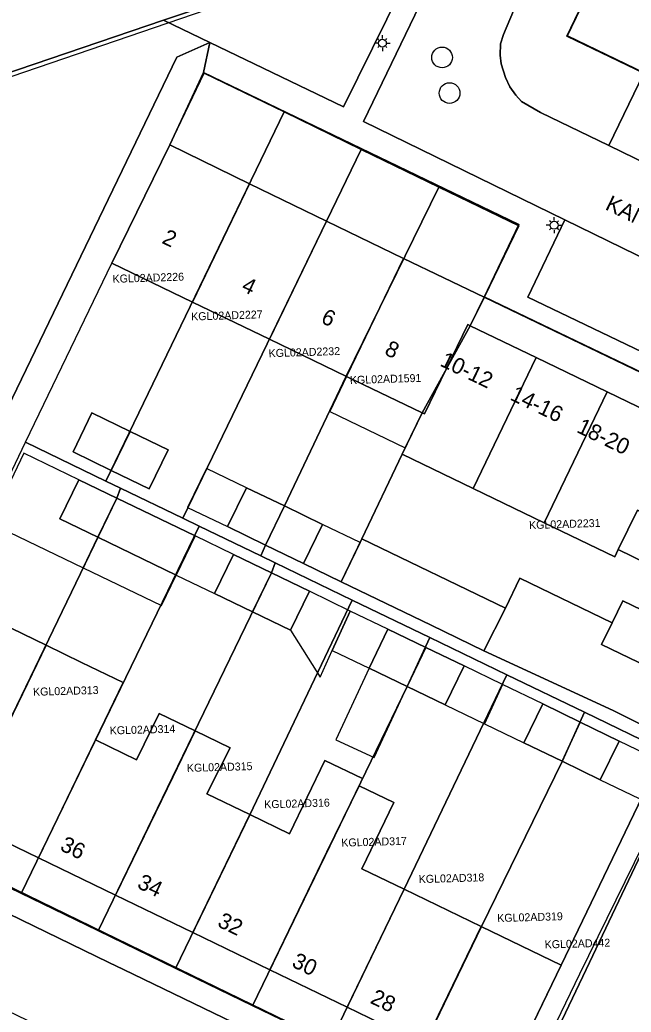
# Model space of a CAD drawing. Extents: x 124901 to 125496, y 515369 to 515789.
# Drawn here: x 125237.2 to 125275.6, y 515497.3 to 515559.7 of the extents above; entities that cross this region are included whole.
import ezdxf

# ---------------------------------------------------------------- set-up
doc = ezdxf.new("R2010")
doc.units = 0
for name, color, linetype in [('Gebouw', 7, 'Continuous'), ('Lichtmast', 7, 'Continuous'), ('Luifel', 7, 'Continuous'), ('Onbegroeid terrein', 7, 'Continuous'), ('Parkeren', 7, 'Continuous'), ('Perceelnummers', 7, 'Continuous'), ('Perceelsgrenzen', 7, 'Continuous'), ('Putten', 7, 'Continuous'), ('Teksten', 7, 'Continuous'), ('Vegetatie', 7, 'Continuous'), ('Voetpad', 7, 'Continuous'), ('Wegen lokale weg', 7, 'Continuous')]:
    doc.layers.add(name, color=color, linetype=linetype)

msp = doc.modelspace()

# ---------------------------------------------------------------- linework, layer by layer
at = {"layer": 'Gebouw'}
for points in [[(125251.606, 515549.402), (125246.6, 515551.84), (125242.94, 515544.4), (125248.008, 515541.962)], [(125252.86, 515539.625), (125256.453, 515547.054), (125251.606, 515549.402), (125248.008, 515541.962)], [(125257.713, 515537.289), (125261.301, 515544.709), (125256.453, 515547.054), (125252.86, 515539.625)], [(125261.301, 515544.709), (125257.713, 515537.289), (125262.47, 515535), (125265.493, 515540.466), (125266.36, 515542.26)], [(125261.21, 515532.39), (125265.676, 515530.239), (125269.642, 515538.465), (125265.493, 515540.466), (125262.47, 515535), (125261.407, 515532.799)], [(125274.106, 515536.313), (125269.642, 515538.465), (125265.676, 515530.239), (125270.14, 515528.089)], [(125277.22, 515531.37), (125278.57, 515534.16), (125274.106, 515536.313), (125270.14, 515528.089), (125274.58, 515525.95), (125274.801, 515526.402), (125276.023, 515528.88), (125278.642, 515527.589), (125279.88, 515530.1)], [(125242.9, 515531.38), (125244.09, 515533.83), (125241.69, 515534.99), (125240.5, 515532.54)], [(125244.09, 515533.83), (125242.9, 515531.38), (125245.3, 515530.22), (125246.49, 515532.67)], [(125243.25, 515529.63), (125240.86, 515530.79), (125239.68, 515528.34), (125242.065, 515527.182)], [(125252.615, 515526.68), (125253.81, 515529.14), (125251.41, 515530.29), (125250.22, 515527.84)], [(125279.717, 515517.905), (125280.762, 515520.078), (125284.72, 515528.31), (125280.11, 515530.54), (125279.88, 515530.1), (125278.642, 515527.589), (125276.023, 515528.88), (125274.801, 515526.402), (125277.47, 515525.11), (125276.256, 515522.602), (125275.09, 515523.17), (125274.418, 515521.801), (125273.75, 515520.44), (125279.58, 515517.62)], [(125243.25, 515529.63), (125242.065, 515527.182), (125246.994, 515524.794), (125248.184, 515527.254)], [(125256.2, 515527.98), (125253.81, 515529.14), (125252.615, 515526.68), (125255.01, 515525.52)], [(125257.38, 515524.38), (125263.03, 515521.64), (125266.35, 515520.04), (125267.7, 515522.72), (125258.68, 515527.07), (125258.567, 515526.835)], [(125252.98, 515524.935), (125250.59, 515526.09), (125249.4, 515523.64), (125251.795, 515522.485)], [(125252.98, 515524.935), (125251.795, 515522.485), (125254.19, 515521.33), (125255.37, 515523.78)], [(125231.937, 515519.018), (125228.44, 515511.8), (125233.472, 515509.364), (125238.814, 515520.386), (125232.953, 515523.225), (125231.109, 515519.419)], [(125262.705, 515520.235), (125260.31, 515521.39), (125259.13, 515518.94), (125261.52, 515517.78)], [(125238.326, 515507.017), (125241.916, 515514.427), (125243.658, 515518.044), (125241.044, 515519.306), (125238.814, 515520.386), (125233.472, 515509.364)], [(125261.52, 515517.78), (125263.92, 515516.63), (125265.1, 515519.08), (125262.705, 515520.235)], [(125272.399, 515515.555), (125270.05, 515516.69), (125268.87, 515514.24), (125271.265, 515513.085)], [(125241.916, 515514.427), (125238.326, 515507.017), (125243.177, 515504.667), (125246.771, 515512.084), (125248.18, 515514.993), (125245.912, 515516.087), (125244.498, 515513.181)], [(125243.177, 515504.667), (125248.033, 515502.323), (125251.623, 515509.733), (125248.91, 515511.048), (125250.387, 515513.928), (125248.18, 515514.993), (125246.771, 515512.084)], [(125274.85, 515514.35), (125272.399, 515515.555), (125271.265, 515513.085), (125273.66, 515511.93)], [(125248.033, 515502.323), (125252.884, 515499.973), (125256.478, 515507.391), (125258.494, 515511.552), (125258.713, 515512.003), (125256.35, 515513.143), (125254.113, 515508.532), (125251.623, 515509.733)], [(125261.332, 515505.044), (125258.673, 515506.33), (125260.689, 515510.489), (125258.494, 515511.552), (125256.478, 515507.391), (125252.884, 515499.973), (125257.74, 515497.62)], [(125262.591, 515495.279), (125266.185, 515502.697), (125261.332, 515505.044), (125257.74, 515497.62)], [(125266.185, 515502.697), (125262.591, 515495.279), (125267.62, 515492.84), (125271.22, 515500.26)]]:
    msp.add_lwpolyline(points, close=True, dxfattribs=at)
at = {"layer": 'Lichtmast'}
for p, q in [((125259.961, 515558.54), (125259.961, 515558.74)), ((125259.661, 515558.241), (125259.461, 515558.24)), ((125259.749, 515558.452), (125259.679, 515558.523)), ((125260.173, 515558.452), (125260.244, 515558.524)), ((125260.261, 515558.24), (125260.461, 515558.24)), ((125259.749, 515558.028), (125259.677, 515557.957)), ((125259.961, 515557.94), (125259.961, 515557.74)), ((125260.173, 515558.028), (125260.243, 515557.957)), ((125270.556, 515547.002), (125270.486, 515547.073)), ((125270.768, 515547.09), (125270.768, 515547.29)), ((125270.98, 515547.002), (125271.051, 515547.074)), ((125270.468, 515546.791), (125270.268, 515546.79)), ((125270.556, 515546.578), (125270.484, 515546.507)), ((125270.768, 515546.49), (125270.768, 515546.29)), ((125270.98, 515546.578), (125271.05, 515546.507)), ((125271.068, 515546.79), (125271.268, 515546.79))]:
    msp.add_line(p, q, dxfattribs=at)
for centre in [(125259.961, 515558.24), (125270.768, 515546.79)]:
    msp.add_circle(centre, 0.25, dxfattribs=at)
at = {"layer": 'Luifel'}
for points in [[(125262.47, 515535), (125257.713, 515537.289), (125256.649, 515535.088), (125261.407, 515532.799)], [(125241.133, 515525.256), (125242.065, 515527.182), (125239.68, 515528.34), (125240.86, 515530.79), (125237.4, 515532.452), (125235.286, 515528.061)], [(125251.41, 515530.29), (125248.903, 515531.503), (125247.713, 515529.053), (125250.22, 515527.84)], [(125258.567, 515526.835), (125256.2, 515527.98), (125255.01, 515525.52), (125257.38, 515524.38)], [(125242.065, 515527.182), (125241.133, 515525.256), (125246.072, 515522.887), (125246.994, 515524.794)], [(125246.994, 515524.794), (125249.4, 515523.64), (125250.59, 515526.09), (125248.184, 515527.254)], [(125254.19, 515521.33), (125256.039, 515518.371), (125256.811, 515520.062), (125257.942, 515522.535), (125255.37, 515523.78)], [(125260.31, 515521.39), (125257.942, 515522.535), (125256.811, 515520.062), (125259.13, 515518.94)], [(125259.13, 515518.94), (125257.038, 515514.439), (125259.448, 515513.319), (125261.52, 515517.78)], [(125266.395, 515515.435), (125267.526, 515517.909), (125265.1, 515519.08), (125263.92, 515516.63)], [(125267.526, 515517.909), (125266.395, 515515.435), (125268.87, 515514.24), (125270.05, 515516.69)], [(125278.251, 515512.708), (125274.85, 515514.35), (125273.66, 515511.93), (125277.13, 515510.255)]]:
    msp.add_lwpolyline(points, close=True, dxfattribs=at)
at = {"layer": 'Onbegroeid terrein'}
for points in [[(125286.39, 515550.48), (125287.283, 515552.328), (125285.12, 515553.38), (125276.89, 515557.33), (125279.14, 515561.97), (125279.58, 515561.75), (125280.85, 515564.41), (125278.06, 515565.76), (125280.2, 515570.2), (125282.34, 515574.64), (125284.5, 515579.14), (125280.805, 515577.895), (125271.575, 515558.685), (125276.419, 515556.359), (125284.626, 515552.418), (125284.179, 515551.548), (125285.039, 515551.133)], [(125251.606, 515549.402), (125256.453, 515547.054), (125261.301, 515544.709), (125266.36, 515542.26), (125268.55, 515546.839), (125248.71, 515556.387), (125246.6, 515551.84)], [(125278.57, 515534.16), (125277.22, 515531.37), (125279.88, 515530.1), (125280.11, 515530.54), (125284.72, 515528.31), (125286.735, 515532.485), (125266.36, 515542.26), (125265.493, 515540.466), (125269.642, 515538.465), (125274.106, 515536.313)], [(125244.09, 515533.83), (125246.49, 515532.67), (125245.3, 515530.22), (125242.9, 515531.38), (125240.5, 515532.54), (125241.69, 515534.99)], [(125240.86, 515530.79), (125243.25, 515529.63), (125248.184, 515527.254), (125246.994, 515524.794), (125242.065, 515527.182), (125239.68, 515528.34)], [(125253.81, 515529.14), (125256.2, 515527.98), (125255.01, 515525.52), (125252.615, 515526.68), (125250.22, 515527.84), (125251.41, 515530.29)], [(125250.59, 515526.09), (125252.98, 515524.935), (125255.37, 515523.78), (125254.19, 515521.33), (125251.795, 515522.485), (125249.4, 515523.64)], [(125263.92, 515516.63), (125261.52, 515517.78), (125259.13, 515518.94), (125260.31, 515521.39), (125262.705, 515520.235), (125265.1, 515519.08)], [(125272.399, 515515.555), (125274.85, 515514.35), (125273.66, 515511.93), (125271.265, 515513.085), (125268.87, 515514.24), (125270.05, 515516.69)]]:
    msp.add_lwpolyline(points, close=True, dxfattribs=at)
for points in [[(125172.485, 515571.333), (125177.633, 515556.026), (125180.878, 515546.433), (125181.828, 515543.598), (125182.601, 515541.383), (125183.083, 515541.545), (125183.744, 515539.581), (125186.768, 515540.688), (125188.276, 515541.173), (125188.453, 515541.235), (125192.866, 515541.235), (125198.77, 515543.221), (125205.934, 515545.686), (125210.005, 515547.087), (125211.259, 515547.465), (125228.842, 515553.805), (125244.154, 515559), (125246.191, 515559.68), (125261.587, 515564.823)], [(125277.47, 515525.11), (125274.801, 515526.402), (125274.58, 515525.95), (125270.14, 515528.089), (125265.676, 515530.239), (125261.21, 515532.39), (125261.407, 515532.799), (125262.47, 515535), (125257.713, 515537.289), (125252.86, 515539.625), (125248.008, 515541.962), (125242.94, 515544.4), (125246.6, 515551.84), (125248.71, 515556.387), (125249.108, 515558.275), (125247.027, 515557.361), (125236.401, 515535.335)], [(125279.347, 515513.859), (125274.477, 515516.274), (125266.35, 515520.04), (125263.03, 515521.64), (125257.38, 515524.38), (125258.567, 515526.835), (125258.68, 515527.07), (125267.7, 515522.72), (125268.609, 515524.604), (125274.418, 515521.801), (125275.09, 515523.17), (125276.256, 515522.602)], [(125232.953, 515523.225), (125238.814, 515520.386), (125241.044, 515519.306), (125243.658, 515518.044), (125241.916, 515514.427), (125244.498, 515513.181), (125245.912, 515516.087), (125248.18, 515514.993), (125250.387, 515513.928), (125248.91, 515511.048), (125251.623, 515509.733), (125254.113, 515508.532), (125256.35, 515513.143), (125258.713, 515512.003), (125258.494, 515511.552), (125260.689, 515510.489), (125258.673, 515506.33), (125261.332, 515505.044), (125266.185, 515502.697), (125271.22, 515500.26), (125267.62, 515492.84)], [(125226.526, 515510.054), (125247.215, 515500), (125266.064, 515490.84), (125267.251, 515490.227), (125267.68, 515490.005), (125269.932, 515494.666), (125270.182, 515494.553), (125272.778, 515500), (125278.716, 515512.461)], [(125262.591, 515495.279), (125257.74, 515497.62), (125252.884, 515499.973), (125248.033, 515502.323), (125243.177, 515504.667), (125238.326, 515507.017), (125233.472, 515509.364)]]:
    msp.add_lwpolyline(points, dxfattribs=at)
at = {"layer": 'Parkeren'}
for points in [[(125274.205, 515551.799), (125283.242, 515547.413), (125285.039, 515551.133), (125284.179, 515551.548), (125284.626, 515552.418), (125276.419, 515556.359)], [(125271.451, 515547.128), (125269.119, 515542.267), (125287.119, 515533.632), (125287.552, 515534.534), (125289.396, 515538.379)], [(125278.716, 515512.461), (125272.778, 515500), (125270.182, 515494.553), (125273.17, 515493.22), (125274.558, 515492.601), (125278.139, 515500), (125283.145, 515510.343)]]:
    msp.add_lwpolyline(points, close=True, dxfattribs=at)
at = {"layer": 'Perceelsgrenzen'}
for points in [[(125173.87, 515567.55), (125166.47, 515589.3), (125198.09, 515599.99), (125199.69, 515595.26), (125243.78, 515610.19), (125254.8, 515577.89), (125258.12, 515579.03), (125262.79, 515565.1), (125211.3, 515547.48), (125216.91, 515544.77), (125221.76, 515542.43), (125226.61, 515540.09), (125231.53, 515537.72), (125236.49, 515535.32), (125230.63, 515523.2), (125224.88, 515511.27), (125219.87, 515513.69), (125215.02, 515516.03), (125210.15, 515518.38), (125205.29, 515520.72), (125198.73, 515523.89), (125209.95, 515547.02), (125185.77, 515538.74), (125175.76, 515568.19)], [(125211.3, 515547.48), (125209.95, 515547.02), (125185.77, 515538.74), (125175.76, 515568.19), (125173.87, 515567.55), (125166.47, 515589.3), (125198.09, 515599.99), (125199.69, 515595.26), (125243.78, 515610.19), (125254.8, 515577.89), (125258.12, 515579.03), (125262.79, 515565.1)], [(125237.52, 515533.15), (125242.94, 515544.4), (125246.6, 515551.84), (125248.75, 515556.35), (125253.786, 515553.911), (125242.565, 515530.708)], [(125258.633, 515551.563), (125247.416, 515528.368), (125243.49, 515530.26), (125242.565, 515530.708), (125253.786, 515553.911)], [(125263.524, 515549.194), (125257.69, 515537.3), (125253.81, 515529.14), (125252.62, 515526.68), (125252.307, 515526.01), (125248.43, 515527.88), (125247.416, 515528.368), (125258.633, 515551.563)], [(125252.62, 515526.68), (125253.81, 515529.14), (125257.69, 515537.3), (125263.524, 515549.194), (125268.55, 515546.76), (125266.39, 515542.3), (125265.49, 515540.46), (125265.34, 515540.54), (125262.62, 515534.93), (125262.47, 515535), (125261.21, 515532.39), (125258.68, 515527.07), (125257.38, 515524.38), (125255.01, 515525.52)], [(125262.94, 515520.87), (125258.07, 515523.22), (125253.22, 515525.57), (125252.307, 515526.01), (125252.62, 515526.68), (125255.01, 515525.52), (125257.38, 515524.38), (125258.68, 515527.07), (125261.21, 515532.39), (125262.47, 515535), (125262.62, 515534.93), (125265.34, 515540.54), (125265.49, 515540.46), (125266.39, 515542.3), (125286.76, 515532.53), (125284.72, 515528.31), (125279.58, 515517.62), (125277.69, 515513.74), (125272.68, 515516.17), (125267.8, 515518.52)], [(125237.52, 515533.15), (125242.565, 515530.708), (125243.49, 515530.26), (125243.25, 515529.63), (125232.37, 515507.12), (125226.46, 515509.99)], [(125232.37, 515507.12), (125243.25, 515529.63), (125243.49, 515530.26), (125247.416, 515528.368), (125248.43, 515527.88), (125237.23, 515504.77)], [(125237.23, 515504.77), (125248.43, 515527.88), (125252.307, 515526.01), (125253.22, 515525.57), (125252.98, 515524.93), (125246.76, 515512.09), (125242.09, 515502.42)], [(125253.22, 515525.57), (125258.07, 515523.22), (125251.63, 515509.73), (125246.95, 515500.06), (125242.09, 515502.42), (125246.76, 515512.09), (125252.98, 515524.93)], [(125251.79, 515497.71), (125246.95, 515500.06), (125251.63, 515509.73), (125258.07, 515523.22), (125262.94, 515520.87), (125261.52, 515517.78)], [(125251.79, 515497.71), (125261.52, 515517.78), (125262.94, 515520.87), (125267.8, 515518.52), (125261.34, 515505.04), (125256.65, 515495.36)], [(125256.65, 515495.36), (125261.34, 515505.04), (125267.8, 515518.52), (125272.68, 515516.17), (125271.27, 515513.08), (125266.2, 515502.69), (125261.52, 515493.01)], [(125261.52, 515493.01), (125266.2, 515502.69), (125271.27, 515513.08), (125272.68, 515516.17), (125277.69, 515513.74), (125277.389, 515513.112), (125271.22, 515500.26), (125266.53, 515490.59)], [(125266.53, 515490.59), (125271.22, 515500.26), (125277.389, 515513.112), (125278.649, 515512.498), (125272.366, 515499.706), (125267.692, 515490.029)]]:
    msp.add_lwpolyline(points, close=True, dxfattribs=at)
for points in [[(125286.81, 515551.36), (125271.62, 515558.71), (125280.85, 515577.9)], [(125286.81, 515551.36), (125271.62, 515558.71), (125280.85, 515577.9)], [(125278.649, 515512.498), (125272.366, 515499.706), (125267.692, 515490.029), (125266.53, 515490.59), (125261.52, 515493.01), (125256.65, 515495.36), (125251.79, 515497.71), (125246.95, 515500.06), (125242.09, 515502.42), (125237.23, 515504.77), (125232.37, 515507.12), (125226.46, 515509.99), (125237.52, 515533.15), (125242.94, 515544.4), (125246.6, 515551.84), (125248.75, 515556.35), (125253.786, 515553.911), (125258.633, 515551.563), (125263.524, 515549.194), (125268.55, 515546.76), (125266.39, 515542.3), (125286.76, 515532.53)]]:
    msp.add_lwpolyline(points, dxfattribs=at)
at = {"layer": 'Putten'}
for centre in [(125263.72, 515557.34), (125264.19, 515555.1)]:
    msp.add_circle(centre, 0.65, dxfattribs=at)
at = {"layer": 'Vegetatie'}
for points in [[(125262.975, 515565.287), (125261.587, 515564.823), (125246.191, 515559.68), (125249.108, 515558.275), (125257.507, 515554.229)], [(125211.259, 515547.465), (125219.656, 515543.346), (125236.401, 515535.335), (125247.027, 515557.361), (125249.108, 515558.275), (125246.191, 515559.68), (125244.154, 515559), (125228.842, 515553.805)], [(125280.979, 515517.296), (125279.717, 515517.905), (125279.58, 515517.62), (125273.75, 515520.44), (125274.418, 515521.801), (125268.609, 515524.604), (125267.7, 515522.72), (125266.35, 515520.04), (125274.477, 515516.274), (125279.347, 515513.859)]]:
    msp.add_lwpolyline(points, close=True, dxfattribs=at)
at = {"layer": 'Voetpad'}
msp.add_lwpolyline([(125274.205, 515551.799), (125276.419, 515556.359), (125271.575, 515558.685), (125280.805, 515577.895), (125284.5, 515579.14), (125285.19, 515580.58), (125279.601, 515583.409), (125278.852, 515581.888), (125281.094, 515580.783), (125272.897, 515564.143), (125270.654, 515565.248), (125268.208, 515560.282), (125267.588, 515558.774), (125267.388, 515558.194), (125267.376, 515557.475), (125267.445, 515556.933), (125267.718, 515556.078), (125267.976, 515555.502), (125268.369, 515554.97), (125268.71, 515554.561), (125269.911, 515553.883)], close=True, dxfattribs=at)
for points in [[(125287.119, 515533.632), (125269.119, 515542.267), (125271.451, 515547.128), (125258.774, 515553.313), (125265.821, 515567.929), (125264.531, 515568.551), (125262.975, 515565.287), (125257.507, 515554.229), (125249.108, 515558.275), (125248.71, 515556.387), (125268.55, 515546.839), (125266.36, 515542.26), (125286.735, 515532.485)], [(125215.942, 515513.474), (125242.758, 515500.446), (125243.68, 515500), (125267.544, 515488.461)], [(125266.064, 515490.84), (125247.215, 515500), (125226.526, 515510.054)]]:
    msp.add_lwpolyline(points, dxfattribs=at)
at = {"layer": 'Wegen lokale weg'}
for points in [[(125275.671, 515588.358), (125274.846, 515586.646), (125274.509, 515585.947), (125265.821, 515567.929), (125258.774, 515553.313), (125271.451, 515547.128), (125289.396, 515538.379)], [(125283.242, 515547.413), (125274.205, 515551.799), (125269.911, 515553.883), (125268.71, 515554.561), (125268.369, 515554.97), (125267.976, 515555.502), (125267.718, 515556.078), (125267.445, 515556.933), (125267.376, 515557.475), (125267.388, 515558.194), (125267.588, 515558.774), (125268.208, 515560.282), (125270.654, 515565.248), (125278.852, 515581.888)], [(125230.99, 515500), (125241.785, 515494.804), (125244.656, 515493.402), (125247.293, 515492.115), (125249.142, 515491.212), (125262.592, 515484.732), (125264.113, 515483.977), (125269.061, 515481.522), (125273.014, 515489.489), (125272.63, 515488.95), (125271.982, 515488.438), (125271.205, 515488.081), (125270.762, 515487.928), (125270.445, 515487.819), (125269.69, 515487.742), (125269.041, 515487.812), (125268.356, 515488.069), (125267.544, 515488.461), (125243.68, 515500), (125242.758, 515500.446), (125215.942, 515513.474)]]:
    msp.add_lwpolyline(points, dxfattribs=at)

# ---------------------------------------------------------------- texts
at = {"layer": 'Perceelnummers'}
for s, rotation, p in [('KGL02AD2226', 1.83088, (125242.996, 515543.169)), ('KGL02AD2227', 1.83094, (125247.942, 515540.8)), ('KGL02AD2232', 1.831, (125252.813, 515538.492)), ('KGL02AD1591', 1.83106, (125257.928, 515536.804)), ('KGL02AD2231', 1.83119, (125269.199, 515527.685)), ('KGL02AD313', 1.63264, (125237.991, 515517.203)), ('KGL02AD314', 1.6327, (125242.816, 515514.77)), ('KGL02AD315', 1.63275, (125247.671, 515512.417)), ('KGL02AD316', 1.63281, (125252.536, 515510.127)), ('KGL02AD317', 1.63287, (125257.386, 515507.718)), ('KGL02AD318', 1.63292, (125262.256, 515505.428)), ('KGL02AD319', 1.63298, (125267.196, 515502.98)), ('KGL02AD442', 1.63302, (125270.181, 515501.318))]:
    msp.add_text(s, height=0.5, rotation=rotation, dxfattribs=at).set_placement(p)
at = {"layer": 'Teksten'}
for s, rotation, p in [('KANTEEL', 334.1, (125273.925, 515547.814)), ('2', 333.8, (125246.033, 515545.699)), ('4', 334.3, (125251.036, 515542.694)), ('6', 334.3, (125256.036, 515540.694)), ('8', 334.3, (125260.036, 515538.694)), ('10-12', 334.3, (125263.524, 515537.983)), ('14-16', 334.3, (125267.936, 515535.846)), ('18-20', 334.3, (125272.125, 515533.806)), ('36', 334.2, (125239.621, 515507.526)), ('34', 334.2, (125244.476, 515505.155)), ('32', 334.2, (125249.524, 515502.735)), ('30', 334.1, (125254.201, 515500.204)), ('28', 334.2, (125259.138, 515497.913))]:
    msp.add_text(s, height=1, rotation=rotation, dxfattribs=at).set_placement(p)

doc.saveas('drawing.dxf')
